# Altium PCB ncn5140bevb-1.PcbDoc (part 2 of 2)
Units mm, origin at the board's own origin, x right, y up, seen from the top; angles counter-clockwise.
Board outline 79 x 79 mm, 2 copper layers (Top Layer, Bottom Layer); 101 components, 67 nets, 300 pads, 331 vias.
Unrouted connection lines stored in the file: 23.
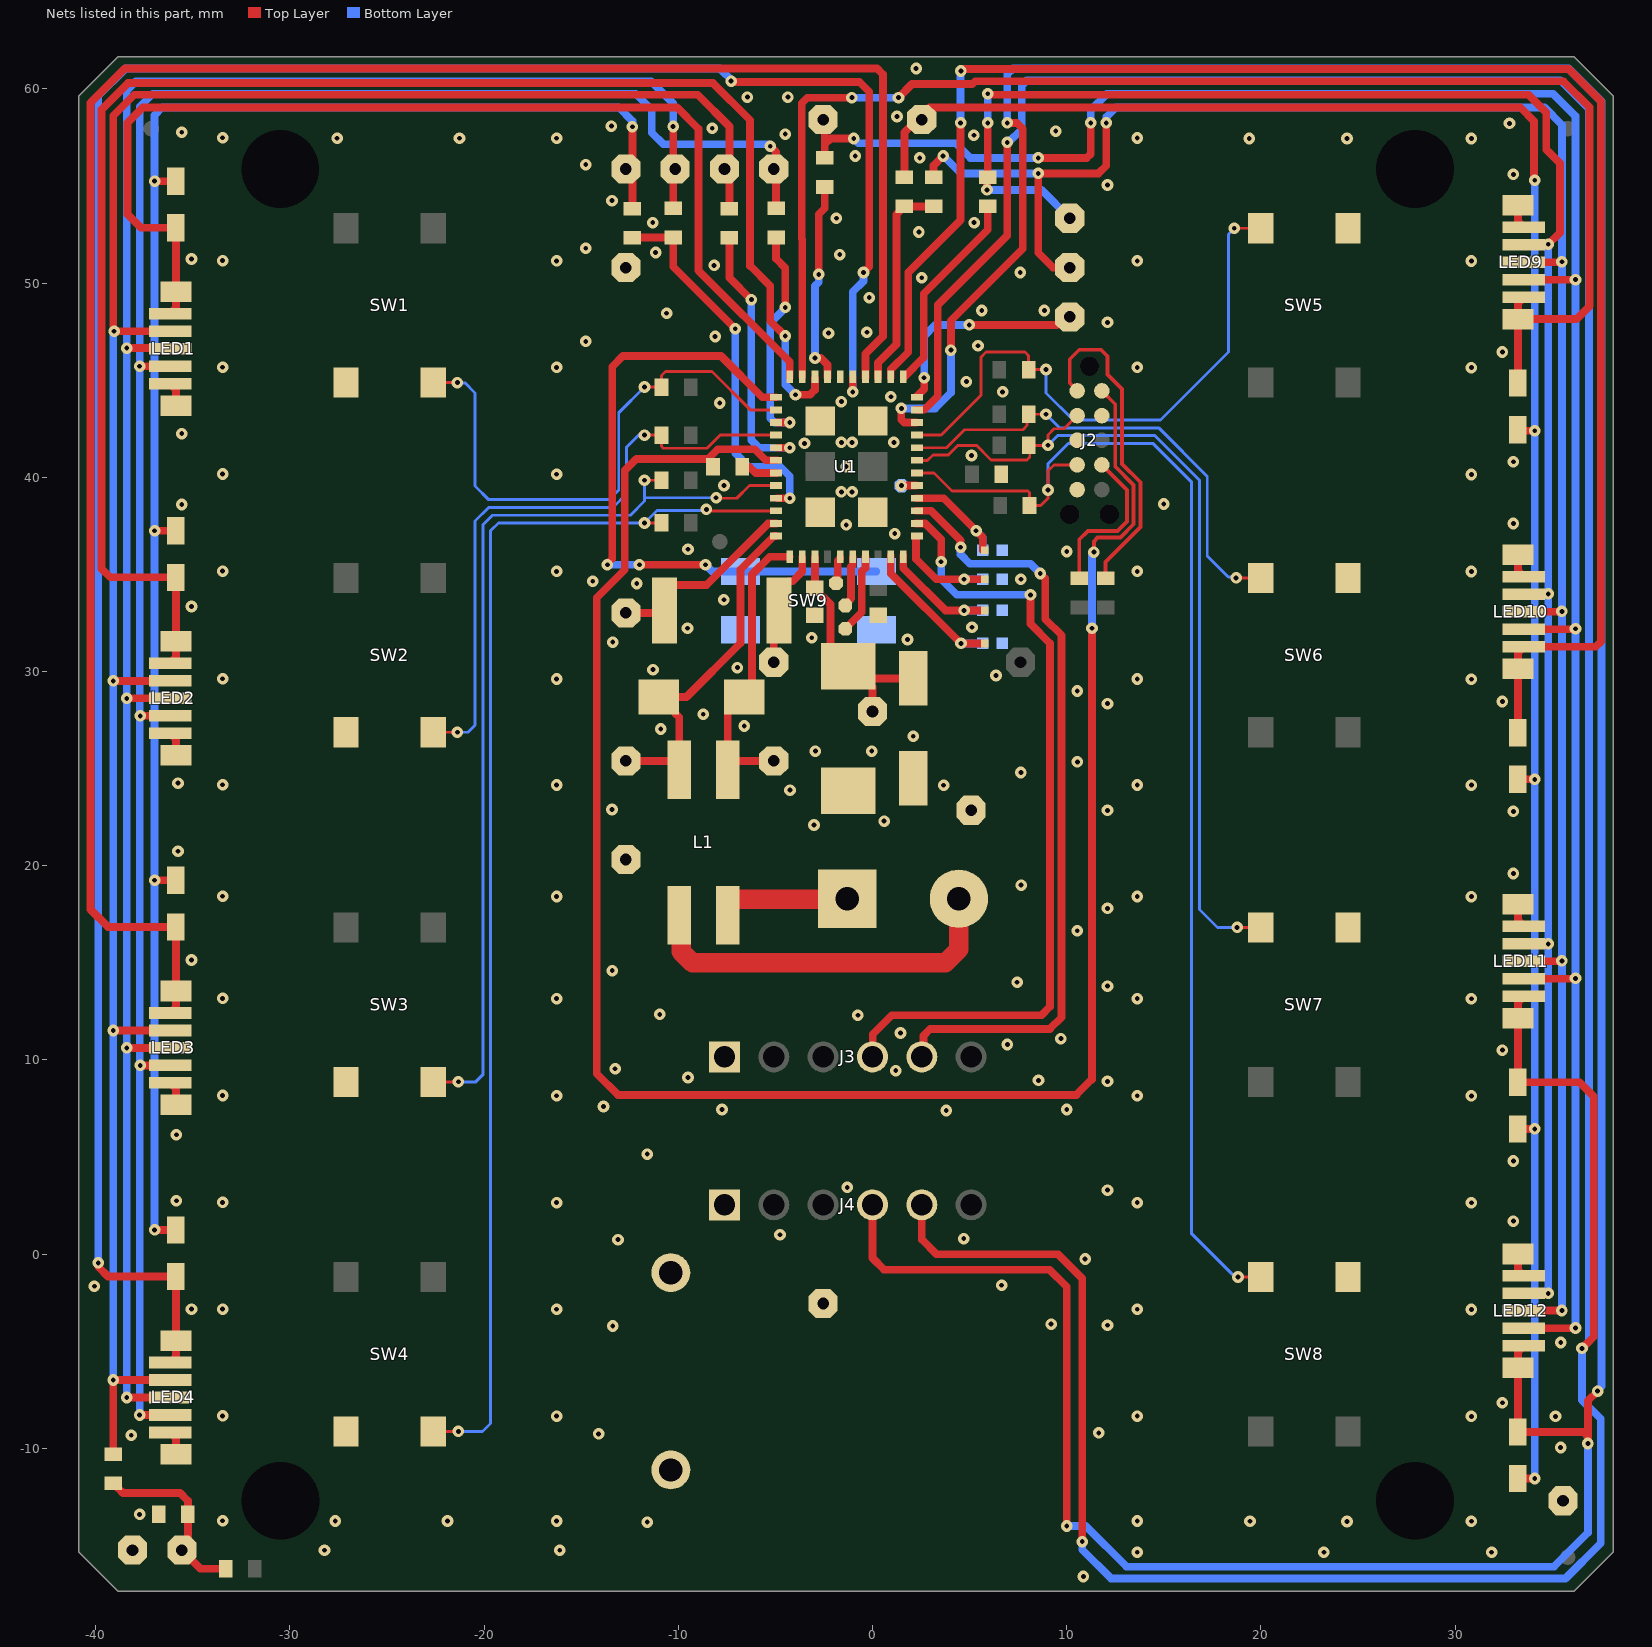
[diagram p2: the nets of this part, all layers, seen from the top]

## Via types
v1: diameter 0.6, hole 0.25, Top Layer to Bottom Layer, tented both sides, 331 vias

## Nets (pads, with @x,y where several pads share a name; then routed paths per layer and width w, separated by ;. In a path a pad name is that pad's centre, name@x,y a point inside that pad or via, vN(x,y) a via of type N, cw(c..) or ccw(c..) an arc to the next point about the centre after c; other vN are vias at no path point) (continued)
GND: C2.1 C3.2 C4.1 C8.2 J2.3 J2.5 J2.9 J3.1 J4.1 NT1.1 NT2.1 NT3.1 NT4.1 R24.1 R25.1 R25.2 R31.2 SW1.1 SW2.1 SW3.1 SW4.1 SW5.1 SW6.1 SW7.1 SW8.1 SW9.3 SW9.4 TP12.1 TP13.1 TP14.1 TP29.1 TP30.1 TP31.1 U1.45 U1.47 U1.48 U1.50
  other v1: 10.86,-16.6 13.637,-15.35 23.244,-15.35 31.881,-15.35 -28.217,-15.244 -16.1,-15.244 -11.6,-13.8 -27.663,-13.739 -21.884,-13.739 -16.263,-13.739 13.637,-13.739 19.437,-13.75 24.437,-13.763 30.837,-13.75 -33.463,-13.729 -37.733,-13.4 35.431,-9.953 -38.163,-9.326 -14.1,-9.256 11.65,-9.2 -33.463,-8.329 -16.263,-8.339 13.637,-8.339 30.837,-8.35 35.168,-8.35 32.437,-7.65 35.437,-4.55 -13.376,-3.7 12.1,-3.663 9.2,-3.6 30.837,-2.85 -35.063,-2.829 -33.463,-2.829 -16.263,-2.839 13.637,-2.839 -40.063,-1.65 6.65,-1.6 10.95,-0.25 -13.1,0.75 4.7,0.8 -4.762,1 33,1.7 30.837,2.644 -33.463,2.665 -16.263,2.655 13.637,2.655 -35.841,2.749 12.1,3.3 -1.3,3.44 33,4.8 -11.6,5.15 -35.841,6.15 3.8,7.4 -7.75,7.45 10,7.45 -13.85,7.6 30.837,8.15 -33.463,8.171 -16.263,8.161 13.637,8.161 12.1,8.9 8.55,8.95 -9.5,9.1 1.2,9.45 -13.25,9.55 32.437,10.504 6.948,10.8 9.7,11.1 1.446,11.386 -0.75,12.3 -10.95,12.35 30.837,13.15 -33.463,13.171 -16.263,13.161 13.637,13.161 12.1,13.8 7.45,14 -13.4,14.6 -35.063,15.15 10.546,16.65 12.099,17.807 30.837,18.409 -33.463,18.43 -16.263,18.419 13.637,18.419 7.652,19 33,19.6 -35.763,20.75 -3.013,22.1 0.598,22.3 33,22.8 12.099,22.85 -13.415,22.9 -4.25,23.897 3.662,24.146 30.837,24.15 -33.463,24.171 -16.263,24.161 13.637,24.161 -35.763,24.253 7.641,24.805 10.55,25.35 -2.939,25.9 -0.039,25.9 2.1,26.672 -10.9,27.04 -6.6,27.2 -8.713,27.8 12.099,28.35 32.437,28.455 10.546,29 -16.263,29.618 13.637,29.618 30.837,29.607 -33.463,29.628 6.358,29.8 -11.3,30.097 -6.958,30.2 -13.376,31.517 1.8,31.65 -3.129,31.739 -9.525,32.229 5.124,32.28 -35.063,33.35 -7.65,33.7 -12.136,34.534 -14.4,34.65 7.641,34.754 30.837,35.15 -33.463,35.171 -16.263,35.161 13.637,35.161 10.004,36.182 -9.5,36.3 1.15,37.1 -1.35,37.55 33,37.625 -35.563,38.6 15,38.631 -1.6,39.25 -1.05,39.25 -7.643,39.58 30.837,40.15 -33.463,40.171 -16.263,40.161 -1.35,40.55 33,40.8 5.1,41.125 -3.5,41.75 -1.6,41.8 -1.05,41.8 1.1,41.8 -35.563,42.25 -7.863,43.824 -1.6,43.9 0.95,44.15 6.7,44.4 4.837,44.927 -33.463,45.671 -16.263,45.661 13.637,45.661 30.837,45.65 32.437,46.45 5.434,46.776 -14.763,46.999 -8.1,47.25 -2.263,47.426 -0.287,47.468 12.099,47.978 -10.6,48.45 5.627,48.594 8.85,48.594 -0.163,49.256 2.537,50.275 7.613,50.55 -8.151,50.916 -16.263,51.148 13.637,51.148 30.837,51.138 -33.463,51.159 -35.063,51.242 -1.687,51.468 -11.163,51.581 -14.763,51.796 2.387,52.636 -11.314,53.113 5.237,53.113 -1.861,53.34 -13.415,54.25 12.099,55.05 33,55.6 -14.763,56.1 2.437,56.45 -0.888,56.55 19.4,57.45 24.437,57.444 30.837,57.45 -27.563,57.461 -21.263,57.461 -16.263,57.461 13.637,57.474 -33.463,57.485 5.223,57.612 -4.492,57.674 -35.563,57.768 9.437,57.825 -8.25,57.974 -13.445,58.087 32.8,58.224 1.262,58.581 -6.44,59.577 -4.354,59.577 2.247,61.05
KNX+: D1.2 L1.2 TP24.1 U1.44 | length 18.7
  Top Layer w0.4: TP24.1@-12.7,25.4 -10.35,25.4 L1.2@-9.95,25 ; D1.2@-11,28.69 D1.2@-10.85,28.69 ; L1.2@-9.95,24.95 L1.2@-9.95,25 ; U1.44@-4.973,36.975 -5.075,36.975 -6.8,35.25 -6.8,31.463 -9.573,28.69 D1.2@-10.85,28.69 ; D1.2@-10.85,28.69 -10.15,27.99 -10.15,27.84 -9.95,27.64 L1.2@-9.95,25
KNX-: D1.1 L1.3 TP25.1 U1.1 | length 15.1
  Top Layer w0.4: D1.1@-7,28.7 -7,28.69 -6.9,28.69 -6.2,29.39 -6.2,35 -5.285,35.915 U1.1@-4.263,35.915 ; D1.1@-6.6,28.69 -6.75,28.69 -6.875,28.565 -7.45,27.99 -7.45,25.4 TP25.1@-5.08,25.4
LS1BC: LED1.5 LED2.5 LED3.5 LED4.5 R7.2 R9.2 TP17.1 | length 117.7
  Top Layer w0.4: R9.2@-39.093,-10.3 v1(-39.093,-6.48) LED4.5@-36.163,-6.48 ; v1(-39.093,11.52) LED3.5@-36.163,11.52 ; v1(-39.093,29.52) LED2.5@-36.163,29.52 ; LED1.5@-36.163,47.52 v1(-39.05,47.52) -39.088,47.558 -39.088,47.7 -39.093,47.704 -39.093,58.62 -38.013,59.7 -9,59.7 -7.363,58.063 R7.2@-7.363,53.84
  Bottom Layer w0.4: v1(-39.093,-6.48) v1(-39.093,11.52) v1(-39.093,29.52) -39.093,47.52 v1(-39.05,47.52)
LS1GC: LED1.3 LED2.3 LED3.3 LED4.3 R6.2 TP16.1 | length 111.5
  Top Layer w0.4: v1(-37.733,-8.28) LED4.3@-36.163,-8.28 ; v1(-37.733,45.72) LED1.3@-36.163,45.72 ; v1(-37.703,9.72) LED3.3@-36.163,9.72 ; v1(-37.703,27.72) LED2.3@-36.163,27.72 ; v1(-5.263,57.05) -4.963,56.75 R6.2@-4.963,53.85
  Bottom Layer w0.4: v1(-37.733,-8.28) v1@-37.733,9.75 ; v1(-37.703,9.72) v1@-37.733,9.75 ; v1(-5.263,57.05) -5.363,57.15 -10.763,57.15 -11.363,57.75 -11.363,58.923 -12.19,59.75 -37.063,59.75 -37.733,59.08 v1(-37.733,45.72) v1@-37.733,9.75
LS1RC: LED1.4 LED2.4 LED3.4 LED4.4 R5.2 TP15.1 | length 110.4
  Top Layer w0.4: v1(-38.395,-7.38) LED4.4@-36.163,-7.38 ; v1(-38.395,10.62) LED3.4@-36.163,10.62 ; v1(-38.395,28.62) LED2.4@-36.163,28.62 ; v1(-38.395,46.653) -36.196,46.653 LED1.4@-36.163,46.62 ; R5.2@-10.263,53.85 v1(-10.263,58.063)
  Bottom Layer w0.4: v1(-38.395,-7.38) v1(-38.395,10.62) v1(-38.395,28.62) v1(-38.395,46.653) -38.395,59.918 -37.922,60.391 -11.404,60.391 -10.263,59.25 v1(-10.263,58.063)
LS2BC: LED9.5 LED10.5 LED11.5 LED12.5 R18.2 TP21.1 | length 117.5
  Top Layer w0.4: TP21.1@-2.6,58.4 -2.463,58.263 -2.463,57.15 ; R18.2@-2.463,56.45 -2.463,57.15 ; v1(-0.963,57.45) -2.163,57.45 -2.463,57.15 ; v1(8.537,56.45) 11.037,56.45 11.237,56.65 v1(11.237,58.25) ; LED12.5@33.537,-3.82 36.18,-3.82 v1(36.2,-3.8) ; LED11.5@33.537,14.18 36.18,14.18 v1(36.2,14.2) ; LED10.5@33.537,32.18 36.18,32.18 v1(36.2,32.2) ; LED9.5@33.537,50.18 v1(36.2,50.18)
  Bottom Layer w0.4: v1(-0.963,57.45) -0.713,57.2 4.287,57.2 5.037,56.45 v1(8.537,56.45) ; v1(11.237,58.25) 11.237,58.913 12.081,59.757 35.043,59.757 36.2,58.6 v1(36.2,50.18) v1(36.2,32.2) v1(36.2,14.2) v1(36.2,-3.8)
LS2GC: LED9.3 LED10.3 LED11.3 LED12.3 R17.2 TP20.1 | length 101.5
  Top Layer w0.4: v1(5.9,54.8) R17.2@5.9,55.4 ; R17.2@5.937,55.45 v1(5.937,58.25) ; v1(5.937,59.75) 5.975,59.712 6.117,59.712 6.128,59.7 33.778,59.7 34.695,58.783 34.695,56.879 35.4,56.173 35.4,52.6 v1(34.8,52) 34.79,51.99 33.547,51.99 LED9.3@33.537,51.98
  Bottom Layer w0.4: v1(5.9,54.8) 8.7,54.8 TP20.1@10.16,53.34 ; v1(5.937,58.25) v1(5.937,59.75) ; v1(34.8,-2.02) 34.8,-1.9 v1(34.8,34) v1(34.8,52)
  other v1: 34.8,15.98
LS2RC: LED9.4 LED10.4 LED11.4 LED12.4 R16.2 TP19.1 | length 111.8
  Top Layer w0.4: R16.2@3.147,55.45 3.147,56.06 v1(3.637,56.55) ; TP19.1@10.2,50.8 TP19.1@10.16,50.8 9.3,50.8 8.537,51.563 v1(8.537,55.65) 11.637,55.65 12.037,56.05 v1(12.037,58.25) ; LED11.4@33.537,15.08 35.48,15.08 v1(35.5,15.1) ; LED10.4@33.537,33.08 35.48,33.08 v1(35.5,33.1) ; LED9.4@33.537,51.08 35.48,51.08 v1(35.5,51.1) ; LED12.4@33.57,-2.953 LED12.4@33.537,-2.92 33.557,-2.9 v1(35.5,-2.9)
  Bottom Layer w0.4: v1(3.637,56.55) 4.537,55.65 v1(8.537,55.65) ; v1(12.037,58.25) 12.037,58.55 12.537,59.05 34.61,59.05 35.5,58.16 v1(35.5,33.1) v1(35.5,15.1) v1(35.5,-2.9)
LS3C: LED5.2 LED6.2 LED7.2 LED8.2 R8.1 TP18.1 | length 91.4
  Top Layer w0.4: v1(-36.963,1.25) LED8.2@-35.863,1.25 ; v1(-36.963,19.25) LED7.2@-35.863,19.25 ; v1(-36.963,37.25) LED6.2@-35.863,37.25 ; v1(-36.963,55.25) LED5.2@-35.863,55.25 ; R8.1@-12.363,53.84 -12.363,55.88 v1(-12.363,58.05)
  Bottom Layer w0.4: v1(-36.963,1.25) v1(-36.963,19.25) v1(-36.963,37.25) v1(-36.963,55.25) -36.963,58.65 -36.563,59.05 -13.063,59.05 -12.363,58.35 v1(-12.363,58.05)
LS4C: LED13.2 LED14.2 LED15.2 LED16.2 R19.1 TP22.1 | length 108.9
  Top Layer w0.4: R19.1@1.647,55.45 1.647,57.76 2.937,59.05 33.35,59.05 34.062,58.338 34.062,55.338 v1(34.1,55.3) ; LED16.2@33.237,-11.55 v1(34.1,-11.55) ; LED15.2@33.237,6.45 v1(34.1,6.45) ; LED14.2@33.237,24.45 v1(34.1,24.45) ; LED13.2@33.237,42.45 33.287,42.4 v1(34.1,42.4)
  Bottom Layer w0.4: v1@34.1,-11.55 v1(34.1,6.45) v1(34.1,24.45) 34.1,24.5 v1(34.1,42.4) v1@34.1,55.3
MODE: NT2.2 SB2.2 U1.9 | length 8.3
  Top Layer w0.4: U1.9@0.937,35.975 0.937,35.05 4.537,31.45 v1(4.562,31.45) SB2.2@5.677,31.45
  Bottom Layer w0.4: v1(4.562,31.45) NT2.2@5.677,31.45
NetC3_1: C3.1 C4.2 C8.1 TP8.1 U1.3 | length 12.1
  Top Layer w0.4: U1.3@-2.963,35.915 C4.2@-2.963,34.3 -2.963,34.263 -2.163,33.463 -2.163,30.771 -1.388,29.996 -1.238,29.996 -0.775,29.996 C3.1@-0.425,29.646 ; TP8.1@0,27.94 0,29.221 C3.1@-0.425,29.646 ; C8.1@2.099,29.646 C3.1@-0.425,29.646
NetJ1_1: J1.1 L1.4 | length 6.9
  Top Layer w1: L1.4@-7.45,17.45 -7.45,18.175 -7.35,18.275 -1.325,18.275 J1.1@-1.3,18.3
NetJ1_2: J1.2 L1.1 | length 19.3
  Top Layer w1: L1.1@-9.95,17.45 -9.85,17.35 -9.85,15.586 -9.264,15 3.75,15 4.45,15.7 J1.2@4.45,18.3
NetJ2_7: J2.7 NT5.1 | length 8.3
  Top Layer w0.2: NT5.1@10.65,34.8 10.65,36.795 11.1,37.245 12.617,37.245 13.1,37.728 13.1,39.351 J2.7@11.811,40.64
NetLED1_1: LED1.1 LED1.2 | length 1.3
  Top Layer w0.4: LED1.2@-36.163,44.82 -35.863,44.52 LED1.1@-35.863,43.69
NetLED2_1: LED2.1 LED2.2 | length 1.3
  Top Layer w0.4: LED2.2@-36.163,26.82 -35.863,26.52 LED2.1@-35.863,25.69
NetLED3_1: LED3.1 LED3.2 | length 1.3
  Top Layer w0.4: LED3.2@-36.163,8.82 -35.863,8.52 LED3.1@-35.863,7.69
NetLED4_1: LED4.1 LED4.2 | length 1.3
  Top Layer w0.4: LED4.2@-36.163,-9.18 -35.863,-9.48 LED4.1@-35.863,-10.31
NetLED9_1: LED9.1 LED9.2 | length 1.3
  Top Layer w0.4: LED9.1@33.237,54.01 33.237,53.18 LED9.2@33.537,52.88
NetLED10_1: LED10.1 LED10.2 | length 1.3
  Top Layer w0.4: LED10.1@33.237,36.01 33.237,35.18 LED10.2@33.537,34.88
NetLED11_1: LED11.1 LED11.2 | length 1.3
  Top Layer w0.4: LED11.1@33.237,18.01 33.237,17.18 LED11.2@33.537,16.88
NetLED12_1: LED12.1 LED12.2 | length 1.3
  Top Layer w0.4: LED12.1@33.237,0.01 33.237,-0.82 LED12.2@33.537,-1.12
NetR9_1: R9.1 R23.1 R24.2 TP23.1 | length 9.3
  Top Layer w0.4: R9.1@-39.093,-11.8 -38.993,-11.8 -38.843,-11.95 -38.843,-12.05 -38.593,-12.3 -35.65,-12.3 -35.25,-12.7 R24.2@-35.25,-13.4 TP23.1@-35.25,-15.05 ; TP23.1@-35.56,-15.24 -34.6,-16.2 R23.1@-33.3,-16.2
NetR32_1: R32.1 U1.39 | length 1.9
  Top Layer w0.4: R32.1@-6.713,40.55 -6.338,40.55 -6.013,40.225 U1.39@-4.913,40.225
NetSW9_1: SW9.1 SW9.2 U1.33 | length 33.9
  Top Layer w0.4: v1(-13.65,35.5) -13.65,35.554 -13.4,35.804 -13.4,45.7 -12.85,46.25 -7.8,46.25 -5.675,44.125 U1.33@-4.973,44.125 ; v1(-12,35.5) v1(-8.6,35.5) v1@-8.638,35.538
  Bottom Layer w0.4: v1(-13.65,35.5) v1(-12,35.5) ; v1(-8.6,35.5) -8.25,35.15 SW9.2@-6.8,35.15 SW9.1@0.2,35.15
NetTP2_1: TP2.1 U1.5 | length 1.4
  Top Layer w0.4: TP2.1@-1.9,34.588 -1.788,34.7 -1.788,35.7 -1.663,35.825 U1.5@-1.663,35.915
NetTP3_1: TP3.1 U1.6 | length 2.7
  Top Layer w0.4: TP3.1@-1.4,33.4 -1.4,33.458 -1.1,33.758 -1.1,35.4 -1.013,35.487 U1.6@-1.013,35.915
NetTP4_1: TP4.1 U1.7 | length 4.1
  Top Layer w0.4: TP4.1@-1.4,32.2 -0.55,33.05 -0.55,35.15 -0.363,35.337 U1.7@-0.363,35.915
P0_0: R13.1 SW6.2 U1.18 | length 24.7
  Top Layer w0.15: U1.18@2.237,41.525 3.812,41.525 4.737,42.45 7.75,42.45 7.963,42.663 7.963,43.176 R13.1@8.037,43.25 v1(8.937,43.25) ; v1(18.725,34.825) SW6.2@19.987,34.825
  Bottom Layer w0.15: v1(8.937,43.25) 9.637,42.55 14.737,42.55 17.237,40.05 17.237,35.95 18.322,34.865 18.685,34.865 v1(18.725,34.825)
P0_1: R12.1 SW5.2 U1.19 | length 30.9
  Top Layer w0.15: U1.19@2.237,42.175 3.537,42.175 5.587,44.225 5.587,46.187 5.85,46.45 7.85,46.45 8.037,46.263 R12.1@8.037,45.55 v1(8.937,45.55) ; v1(18.625,52.825) SW5.2@19.987,52.825
  Bottom Layer w0.15: v1(8.937,45.55) 8.937,44.35 10.337,42.95 14.837,42.95 18.337,46.45 18.337,52.512 18.625,52.8 v1(18.625,52.825)
P0_4/TRACE: J4.4 LED12.6 LED12.7 LED16.1 U1.20 | length 190.6
  Top Layer w0.4: J4.4@0,2.54 0,-0.2 0.6,-0.8 9.117,-0.8 10,-1.683 v1(10,-14) ; v1(1.487,43.55) 1.487,42.975 1.637,42.825 U1.20@2.237,42.825 ; v1(4.037,46.55) 4.037,48.067 7.737,51.767 7.737,57.95 7.437,58.25 v1(6.937,58.25) ; LED12.6@33.537,-4.72 33.237,-5.02 LED12.7@33.237,-5.85 LED16.1@33.237,-9.15 36.602,-9.15 36.837,-9.385 ; v1(36.837,-9.75) 36.837,-9.385 ; v1(37.337,-7.05) 36.837,-7.55 36.837,-9.385
  Bottom Layer w0.4: v1(1.487,43.55) 3.237,43.55 4.037,44.35 v1(4.037,46.55) ; v1(6.937,58.25) 6.937,60.75 7.237,61.05 12.437,61.05 35.837,61.05 37.537,59.35 37.537,-6.796 37.337,-6.996 v1(37.337,-7.05) ; v1(10,-14) 10.987,-14 13.087,-16.1 35.087,-16.1 36.837,-14.35 v1(36.837,-9.75)
P0_5/TRACE: J4.5 LED11.6 LED11.7 LED15.1 U1.21 | length 198.5
  Top Layer w0.4: U1.21@2.237,43.475 2.662,43.475 3.362,44.175 3.362,48.875 6.937,52.45 v1(6.937,57.25) ; J4.5@2.54,2.54 2.54,0.76 3.3,0 9.55,0 10.8,-1.25 v1(10.8,-14.8) ; LED11.6@33.537,13.28 33.237,12.98 LED11.7@33.237,12.15 LED15.1@33.237,8.85 36.407,8.85 37.137,8.12 37.137,-4.25 v1(36.537,-4.85)
  Bottom Layer w0.4: v1(6.937,57.25) 7.007,57.25 7.687,57.93 7.687,60.174 7.963,60.45 12.337,60.45 34.337,60.45 35.41,60.45 36.9,58.96 36.9,-4.487 v1(36.537,-4.85) 36.537,-7.515 37.5,-8.478 37.5,-14.887 35.687,-16.7 12.287,-16.7 10.8,-15.213 v1(10.8,-14.8)
P1_0: R17.1 U1.23 | length 10.5
  Top Layer w0.4: U1.23@1.647,45.185 2.637,46.175 2.637,49.45 5.937,52.75 R17.1@5.937,53.95
P1_1: LED10.6 LED10.7 LED14.1 U1.24 | length 87.4
  Top Layer w0.4: U1.24@0.937,45.125 0.937,45.55 1.837,46.45 1.837,50.55 4.537,53.25 v1(4.537,58.25) ; v1(4.551,60.925) 4.652,61.026 35.847,61.026 37.517,59.355 37.517,31.55 37.247,31.28 LED10.6@33.537,31.28 33.237,30.98 LED10.7@33.237,30.15 LED14.1@33.237,26.85
  Bottom Layer w0.4: v1(4.537,58.25) 4.537,60.911 v1(4.551,60.925)
P1_2: R16.1 R19.2 U1.25 | length 10.9
  Top Layer w0.4: U1.25@0.287,45.125 U1.25@0.287,45.185 0.287,45.9 1.237,46.85 1.237,53.54 R19.2@1.647,53.95 R16.1@3.147,53.95
P1_3: LED3.6 LED3.7 LED7.1 U1.26 | length 108.5
  Top Layer w0.4: LED3.6@-36.163,12.42 -35.863,12.72 LED3.7@-35.863,13.55 LED7.1@-35.863,16.85 -39.363,16.85 -40.263,17.75 -40.263,59.28 -38.493,61.05 0.237,61.05 0.537,60.75 0.537,47.25 -0.363,46.35 U1.26@-0.363,45.125
P1_4: R18.1 U1.29 | length 10.5
  Top Layer w0.4: v1(-2.963,46.147) -2.66,46.147 -2.313,45.8 U1.29@-2.313,45.185 U1.29@-2.313,45.125 ; v1(-2.763,50.45) -2.763,53.55 -2.463,53.85 R18.1@-2.463,54.95
  Bottom Layer w0.4: v1(-2.963,46.147) -2.963,49.85 -2.763,50.05 v1(-2.763,50.45)
P1_5: LED2.6 LED2.7 LED6.1 U1.30 | length 83.8
  Top Layer w0.4: LED2.6@-36.163,30.42 -35.863,30.72 LED2.7@-35.863,31.55 LED6.1@-35.863,34.85 -39.252,34.85 -39.7,35.298 -39.7,58.934 -38.334,60.3 -8.213,60.3 -6.3,58.387 -6.3,50.887 -5.263,49.85 -5.263,48.045 v1(-4.492,47.274) ; v1(-3.963,44.25) -3.215,44.25 -2.963,44.502 U1.30@-2.963,45.125
  Bottom Layer w0.4: v1(-4.492,47.274) -4.492,44.779 v1(-3.963,44.25)
P1_6: LED9.6 LED9.7 LED13.1 U1.31 | length 74.4
  Top Layer w0.4: U1.31@-3.613,45.185 -3.613,52.254 -3.64,52.281 -3.64,59.26 -3.35,59.55 v1(-1.063,59.55) ; v1(1.337,59.55) 2.037,60.25 5.137,60.25 5.287,60.4 35.577,60.4 36.918,59.059 36.918,48.812 36.256,48.15 LED9.7@33.237,48.15 ; LED13.1@33.237,44.85 LED9.7@33.237,48.15 ; LED9.6@33.537,49.28 33.237,48.98 LED9.7@33.237,48.15
  Bottom Layer w0.4: v1(-1.063,59.55) v1(1.337,59.55)
P1_7: LED1.6 LED1.7 LED5.1 U1.32 | length 57
  Top Layer w0.4: LED1.6@-36.163,48.42 -35.863,48.72 LED1.7@-35.863,49.55 LED5.1@-35.863,52.85 -37.663,52.85 -38.363,53.55 -38.363,58.25 -37.563,59.05 -10.063,59.05 -8.963,57.95 -8.963,50.65 -4.263,45.95 U1.32@-4.263,45.125
P2_1: R1.1 SW1.2 U1.34 | length 29.2
  Top Layer w0.15: SW1.2@-22.613,44.875 v1(-21.375,44.875) ; v1(-11.738,44.65) R1.1@-10.863,44.65 -10.863,45.237 -10.65,45.45 -8.263,45.45 -6.288,43.475 U1.34@-4.913,43.475
  Bottom Layer w0.15: v1(-21.375,44.875) -21.347,44.847 -20.96,44.847 -20.463,44.35 -20.463,39.55 -19.763,38.85 -13.563,38.85 -13.063,39.35 -13.063,43.325 v1(-11.738,44.65)
P2_2: R6.1 U1.35 | length 11.6
  Top Layer w0.4: R6.1@-4.963,52.35 -4.963,51.25 -4.492,50.779 v1(-4.492,48.75) ; U1.35@-4.913,42.825 v1(-4.263,42.825)
  Bottom Layer w0.4: v1(-4.492,48.75) -4.492,48.721 -5.263,47.95 -5.263,43.05 -5.038,42.825 v1(-4.263,42.825)
P2_3: R2.1 SW2.2 U1.36 | length 32.5
  Top Layer w0.15: SW2.2@-22.613,26.875 v1(-21.375,26.875) ; v1(-11.738,42.175) R2.1@-10.863,42.175 -10.863,41.588 -10.775,41.5 -8.514,41.5 -7.839,42.175 U1.36@-4.913,42.175
  Bottom Layer w0.15: v1(-21.375,26.875) -20.825,26.875 -20.463,27.237 -20.463,36.95 -20.463,37.75 -19.763,38.45 -13.363,38.45 -12.663,39.15 -12.663,41.55 -12.038,42.175 v1(-11.738,42.175)
P2_4: R7.1 U1.37 | length 13.7
  Top Layer w0.4: R7.1@-7.363,52.34 -7.363,50.275 v1(-6.238,49.15) ; U1.37@-4.913,41.525 v1(-4.263,41.525)
  Bottom Layer w0.4: v1(-6.238,49.15) -6.238,41.925 -5.838,41.525 v1(-4.263,41.525)
P2_5: R3.1 SW3.2 U1.40 | length 48.9
  Top Layer w0.15: SW3.2@-22.613,8.875 v1(-21.325,8.875) ; v1(-11.738,39.85) R3.1@-10.863,39.85 ; v1(-8.05,38.95) -8.025,38.925 -6.988,38.925 -6.338,39.575 U1.40@-4.913,39.575
  Bottom Layer w0.15: v1(-21.325,8.875) -20.425,8.875 -20.063,9.237 -20.063,37.55 -19.563,38.05 -12.463,38.05 -11.738,38.775 -11.738,38.95 ; v1(-11.738,39.85) -11.738,38.95 ; v1(-8.05,38.95) -11.738,38.95
P2_6: R5.1 R8.2 U1.41 | length 19.6
  Top Layer w0.4: R8.2@-12.363,52.34 -12.353,52.35 R5.1@-10.263,52.35 -10.263,50.85 v1(-7.063,47.65) ; U1.41@-4.913,38.925 v1(-4.263,38.925)
  Bottom Layer w0.4: v1(-7.063,47.65) -7.063,41.25 -6.363,40.55 -4.763,40.55 -4.263,40.05 v1(-4.263,38.925)
P2_7: R4.1 SW4.2 U1.42 | length 65.2
  Top Layer w0.15: SW4.2@-22.613,-9.125 v1(-21.325,-9.125) ; v1(-11.738,37.65) R4.1@-10.863,37.65 ; v1(-8.55,38.35) -8.475,38.275 U1.42@-4.913,38.275
  Bottom Layer w0.15: v1(-21.325,-9.125) -20.075,-9.125 -19.663,-8.713 -19.663,37.25 -19.263,37.65 v1(-11.738,37.65) -11.088,38.3 -8.6,38.3 v1(-8.55,38.35)
P3_2/SWDIO: J2.2 R14.1 SW7.2 U1.17 | length 45.2
  Top Layer w0.15: U1.17@2.297,40.875 2.837,40.875 3.112,41.15 3.9,41.15 4.4,41.65 5.35,41.65 6.1,40.9 7.95,40.9 8.1,41.05 8.1,41.587 R14.1@8.037,41.65 v1(9.037,41.65) 9.037,42.187 9.35,42.5 9.861,42.5 J2.2@10.541,43.18 ; v1(18.775,16.825) SW7.2@19.987,16.825
  Bottom Layer w0.15: v1(9.037,41.65) 9.537,42.15 14.537,42.15 16.837,39.85 16.837,17.75 17.762,16.825 v1(18.775,16.825)
P3_3/SWDCLK: J2.4 R15.1 SW8.2 U1.16 | length 64.2
  Top Layer w0.15: U1.16@2.297,40.225 3.172,40.225 4.097,39.3 7.999,39.3 8.087,39.212 R15.1@8.087,38.55 8.662,38.55 9.037,38.925 v1(9.037,39.35) 9.037,40.337 9.34,40.64 J2.4@10.541,40.64 ; v1(18.825,-1.175) SW8.2@19.987,-1.175
  Bottom Layer w0.15: v1(9.037,39.35) 9.037,40.698 10.089,41.75 14.437,41.75 16.437,39.75 16.437,1.05 18.522,-1.035 18.564,-1.035 18.703,-1.175 v1(18.825,-1.175)
P4_2: U1.28
P4_3: LED4.6 LED4.7 LED8.1 U1.27 | length 126.5
  Top Layer w0.4: v1(-39.863,-0.45) -39.863,-0.65 -39.363,-1.15 LED8.1@-35.863,-1.15 LED4.7@-35.863,-4.45 -35.863,-5.28 LED4.6@-36.163,-5.58 ; v1(-7.278,60.4) -7.228,60.35 -0.663,60.35 -0.163,59.85 -0.163,50.85 v1(-0.463,50.55) ; v1(-1.013,44.4) U1.27@-1.013,45.125
  Bottom Layer w0.4: v1(-39.863,-0.45) -39.863,59.65 -38.463,61.05 -7.851,61.05 -7.201,60.4 v1(-7.278,60.4) ; v1(-1.013,44.4) -1.013,49.55 -0.463,50.1 v1(-0.463,50.55)
RSTBIN: J2.10 R32.2 U1.38 | length 104.2
  Top Layer w0.2: v1(11.4,36.15) 11.4,36.7 11.595,36.895 12.762,36.895 13.45,37.583 13.45,39.6 12.5,40.55 12.5,43.761 J2.10@11.811,44.45
  Top Layer w0.4: U1.38@-4.913,40.875 -5.488,40.875 -6.063,41.45 -7.963,41.45 -8.463,40.95 -12.15,40.95 -12.75,40.35 -12.75,35.25 -14.2,33.8 -14.2,9.294 -13.106,8.2 10.5,8.2 11.3,9 v1(11.3,32.229)
  Bottom Layer w0.4: v1(11.3,32.229) 11.3,36.05 v1(11.4,36.15)
TREQ: NT1.2 SB1.2 U1.10 | length 6.6
  Top Layer w0.4: U1.10@1.587,35.975 1.587,35.325 3.762,33.15 v1(4.719,33.15) SB1.2@5.677,33.15
  Bottom Layer w0.4: v1(4.719,33.15) NT1.2@5.677,33.15
TRX_RXD: J3.4 U1.12 | length 41.1
  Top Layer w0.4: J3.4@0,10.16 0.02,10.18 0.02,11.32 1,12.3 8.7,12.3 9.137,12.737 9.137,31.463 8.137,32.463 v1(8.137,33.95) ; U1.12@2.237,37.625 U1.12@2.297,37.625 2.712,37.625 3.537,36.8 v1(3.537,35.65)
  Bottom Layer w0.4: v1(3.537,35.65) 3.537,34.75 4.337,33.95 v1(8.137,33.95)
TRX_TXD: J3.5 U1.13 | length 40.1
  Top Layer w0.4: U1.13@2.237,38.275 3.012,38.275 4.537,36.75 v1(4.537,36.4) ; J3.5@2.54,10.16 2.63,10.25 2.63,11.25 2.98,11.6 9.137,11.6 9.737,12.2 9.737,31.863 8.9,32.7 8.9,34.787 v1(8.637,35.05)
  Bottom Layer w0.4: v1(4.537,36.4) 4.537,36.025 5.012,35.55 8.137,35.55 v1(8.637,35.05)
TXO: R33.1 TP7.1 U1.43 | length 10.1
  Top Layer w0.4: TP7.1@-12.7,33.02 -10.843,33.02 R33.1@-10.713,33.15 -10.713,34 -10.263,34.45 -8.55,34.45 -5.375,37.625 U1.43@-4.973,37.625
UC1: NT3.2 SB3.2 U1.11 | length 5.9
  Top Layer w0.4: U1.11@2.237,36.915 2.237,35.8 3.287,34.75 v1(4.72,34.75) SB3.2@5.677,34.75
  Bottom Layer w0.4: v1(4.72,34.75) NT3.2@5.677,34.75
UC2: NT4.2 SB4.2 U1.14 | length 6.1
  Top Layer w0.4: U1.14@2.237,38.925 3.662,38.925 v1(5.337,37.25) 5.677,36.91 SB4.2@5.677,36.25
  Bottom Layer w0.4: v1(5.337,37.25) 5.677,36.91 NT4.2@5.677,36.25
VBUS1: R33.2 TP6.1 U1.2 | length 6.2
  Top Layer w0.4: TP6.1@-5.08,30.48 -5.08,32.883 R33.2@-4.813,33.15 -4.813,34.2 -4.363,34.65 -4.113,34.65 -3.613,35.15 U1.2@-3.613,35.915
VTREF: J2.1 R26.1 | length 17
  Top Layer w0.2: J2.1@10.541,44.45 10.541,44.486 10.16,44.867 10.16,46.08 10.65,46.57 11.767,46.57 12.1,46.237 12.1,45.3 12.85,44.55 12.85,40.695 13.8,39.745 13.8,37.438 12,35.638 R26.1@12,34.8
XCLK: TP11.1 U1.22 | length 11.1
  Top Layer w0.4: U1.22@2.297,44.185 2.662,44.55 v1(2.662,45.125) ; v1(4.987,47.85) 9.492,47.85 9.902,48.26 TP11.1@10.16,48.26
  Bottom Layer w0.4: v1(2.662,45.125) 2.662,47.275 3.237,47.85 v1(4.987,47.85)
XTAL2: TP10.1 U1.15 | length 0.7
  Top Layer w0.4: v1(1.487,39.575) U1.15@2.237,39.575
pads on no net: J2.6 J2.8 J2.A J2.B J2.C J3.2 J3.3 J3.6 J4.2 J4.3 J4.6 SW1.3 SW1.4 SW2.3 SW2.4 SW3.3 SW3.4 SW4.3 SW4.4 SW5.3 SW5.4 SW6.3 SW6.4 SW7.3 SW7.4 SW8.3 SW8.4

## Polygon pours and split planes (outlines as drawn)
GND on Top Layer "Top full copper" (solid, remove dead copper, pour order 92): -40.863,-17.35 38.137,-17.35 38.137,61.65 -40.863,61.65
GND on Top Layer "Top CapSense GND 1" (hatched 45Degree grid 1.143 track 0.178, remove dead copper, pour order 81): 31.237,-14.15 31.237,57.85 13.237,57.85 13.25,45.487 14,44.737 13.995,40.995 14.689,40.3 14.689,36.839 13.25,35.4 13.237,-14.15
GND on Top Layer "Top CapSense GND 2" (hatched 45Degree grid 1.143 track 0.178, remove dead copper, pour order 79): -15.863,-14.15 -15.863,57.85 -33.863,57.85 -33.863,-14.15
GND on Top Layer "FANIN GND" (solid, remove dead copper, pour order 101): 3.7,42.05 8.4,42.05 8.4,39.05 3.7,39.05
GND on Bottom Layer "Bottom Layer-GND" (solid, remove dead copper, pour order 94): -40.863,61.65 38.137,61.65 38.137,-17.35 -40.863,-17.35
GND on Bottom Layer "Bottom CapSense GND 2" (hatched 45Degree grid 1.778 track 0.178, remove dead copper, pour order 89): 31.237,-14.15 31.237,57.85 13.237,57.85 13.237,46.85 7.737,46.85 7.737,39.05 1.262,39.05 1.262,37.35 13.237,37.35 13.237,-14.15
GND on Bottom Layer "Bottom CapSense GND 1" (hatched 45Degree grid 1.778 track 0.178, remove dead copper, pour order 83): -33.863,-14.161 -15.863,-14.161 -15.863,36.839 -10.363,36.839 -10.363,36.939 -3.663,36.939 -3.663,38.939 -10.363,38.939 -10.363,45.839 -15.863,45.839 -15.863,57.839 -33.863,57.839
GND on Bottom Layer "Bottom Layer-GND 2" (solid, remove dead copper, pour order 100): -5.779,39.857 -1.35,39.857 -1.35,35.9 -5.779,35.9
GND on Bottom Layer "Bottom Layer-GND 1" (solid, remove dead copper, pour order 102): 0.118,40.55 5.05,40.55 5.05,36.443 0.118,36.443

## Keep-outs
Top Layer:
  lines w0.1: -4.913,44.224 -4.913,45.125 ; -34.363,-14.65 -34.363,58.35 -15.363,58.35 -15.363,-14.65 -34.363,-14.65 ; 12.737,-14.65 12.737,35.592 14.2,37.055 14.2,40.041 13.3,40.941 13.3,44.737 12.737,45.3 12.737,58.35 31.737,58.35 31.737,-14.65 12.737,-14.65
Bottom Layer:
  lines w0.1: -5.663,36.95 -10.263,36.95 -10.263,36.35 -15.363,36.35 -15.363,-14.65 -34.363,-14.65 -34.363,58.35 -15.363,58.35 -15.363,46.35 -10.263,46.35 -10.263,38.95 -5.663,38.95 ; 4.537,36.825 7.237,36.825 12.737,36.825 12.737,-14.65 31.737,-14.65 31.737,58.35 12.737,58.35 12.737,47.348 7.215,47.348 7.215,39.55 4.937,39.55

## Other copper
Top Layer:
  pour cut-out: 35.084,57.95 ccw(c35.8,57.95) 35.8,57.234 ccw(c35.8,57.95) 36.516,57.95 ccw(c35.8,57.95) 35.8,58.666 ccw(c35.8,57.95)
  pour cut-out: -37.854,57.95 ccw(c-37.139,57.95) -37.139,57.234 ccw(c-37.139,57.95) -36.423,57.95 ccw(c-37.139,57.95) -37.139,58.666 ccw(c-37.139,57.95)
  pour cut-out: 35.082,-15.6 ccw(c35.798,-15.6) 35.798,-16.316 ccw(c35.798,-15.6) 36.514,-15.6 ccw(c35.798,-15.6) 35.798,-14.884 ccw(c35.798,-15.6)
  pour cut-out: -8.579,36.689 ccw(c-7.863,36.689) -7.863,35.973 ccw(c-7.863,36.689) -7.147,36.689 ccw(c-7.863,36.689) -7.863,37.404 ccw(c-7.863,36.689)
  pour cut-out: -11.481,19.472 -11.49,13.55 6.825,13.55 6.825,21.139 -5.715,21.15 -5.707,24.493 -11.474,24.493
  region net NetR9_1: -14.7,-14.6
  text "L1" at 7.462,2.095 h1
Bottom Layer:
  pour cut-out: -11.481,19.472 -11.49,13.55 6.825,13.55 6.825,21.139 -5.715,21.15 -5.707,24.493 -11.474,24.493
  region: 14.837,25.75
  region net GND: -0.338,38.6
  text "L2" at 11.006,2.095 h1

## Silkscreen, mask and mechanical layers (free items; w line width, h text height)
Top Overlay:
  circle w0.3: c-30.48,-12.7 r2.51
  circle w0.3: c27.94,-12.7 r2.51
  circle w0.3: c27.94,55.88 r2.51
  circle w0.3: c-30.49,55.88 r2.51
  rectangle: -8,-13.4 11.7,-4.15
  lines w0.1: -33.863,-14.15 -15.863,-14.15 -15.863,-5.15 -15.863,53.85 -15.863,57.85 -29.863,57.85 -33.863,57.85 -33.863,-10.15 -33.863,-14.15 ; 13.237,-14.15 13.237,-10.15 13.237,57.85 17.237,57.85 31.237,57.85 31.237,53.85 31.237,-5.15 31.237,-14.15 13.237,-14.15
  lines w0.2: -34.544,-16.256 -34,-16.8 -22.65,-16.8 ccw(c-22.65,-16.25) -22.1,-16.25 -22.1,-14.35 ; 2.2,32.385 2.2,31.313 ccw(c2.36,31.313) 2.247,31.2 ccw(c2.368,31.321) 2.368,31.15 3.05,31.15 3.25,30.95 6.604,30.95 ; 2.4,35.15 2.4,33.7 ccw(c2.75,33.7) 2.75,33.35 3.75,33.35 cw(c3.75,32.162) 4.59,33.002 4.7,32.892 ccw(c5.284,33.476) 5.284,32.65 6.985,32.65 ; 2.5,32.004 ccw(c2.504,32.004) 2.504,32 ; 5.2,34.3 6.737,34.3 cw(c6.737,33.9) 7.137,33.9 ccw(c7.337,33.9) 7.337,33.7 9.2,33.7 ; 5.2,35.8 9.2,35.8 ; 9.8,9.248 cw(c11.49,10.938) 9.1,10.938 9.1,23.612 cw(c12.166,23.612) 9.998,25.78 10.668,26.45 ccw(c8.901,28.217) 11.4,28.217 11.4,32.65 ccw(c11.25,32.65) 11.25,32.8 ; 11.25,32.8 10.05,32.8 10.05,35.3 10.15,35.3 11.25,35.3 11.25,32.8
  text ".ProjectBoardName / '.Print_Date'" at 17.237,58.35 h1
  text "Cut to disconnect / debugger supply" at 9.144,25.65 h1 r270
  text "SiP UART" at -5.263,7.27 h1
  text "TRX_TXD" at -0.338,7.161 h1 r50
  text "TRX_RXD" at 0,6.3 h1 r80
  text "P0_5" at 3.05,3.75 h1 r45
  text "P0_4" at -0.25,2.75 h1 r45
  text "TRACE UART" at -6.038,-0.2 h1
  text "'.ProjectTitle'" at -5.9,-16.7 h1
Top Solder:
  rectangle: 7.012,1.645 11.411,3.545
Bottom Solder:
  rectangle: 7.012,1.645 11.411,3.545
Route Tool Path:
  the board outline again, w0.2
